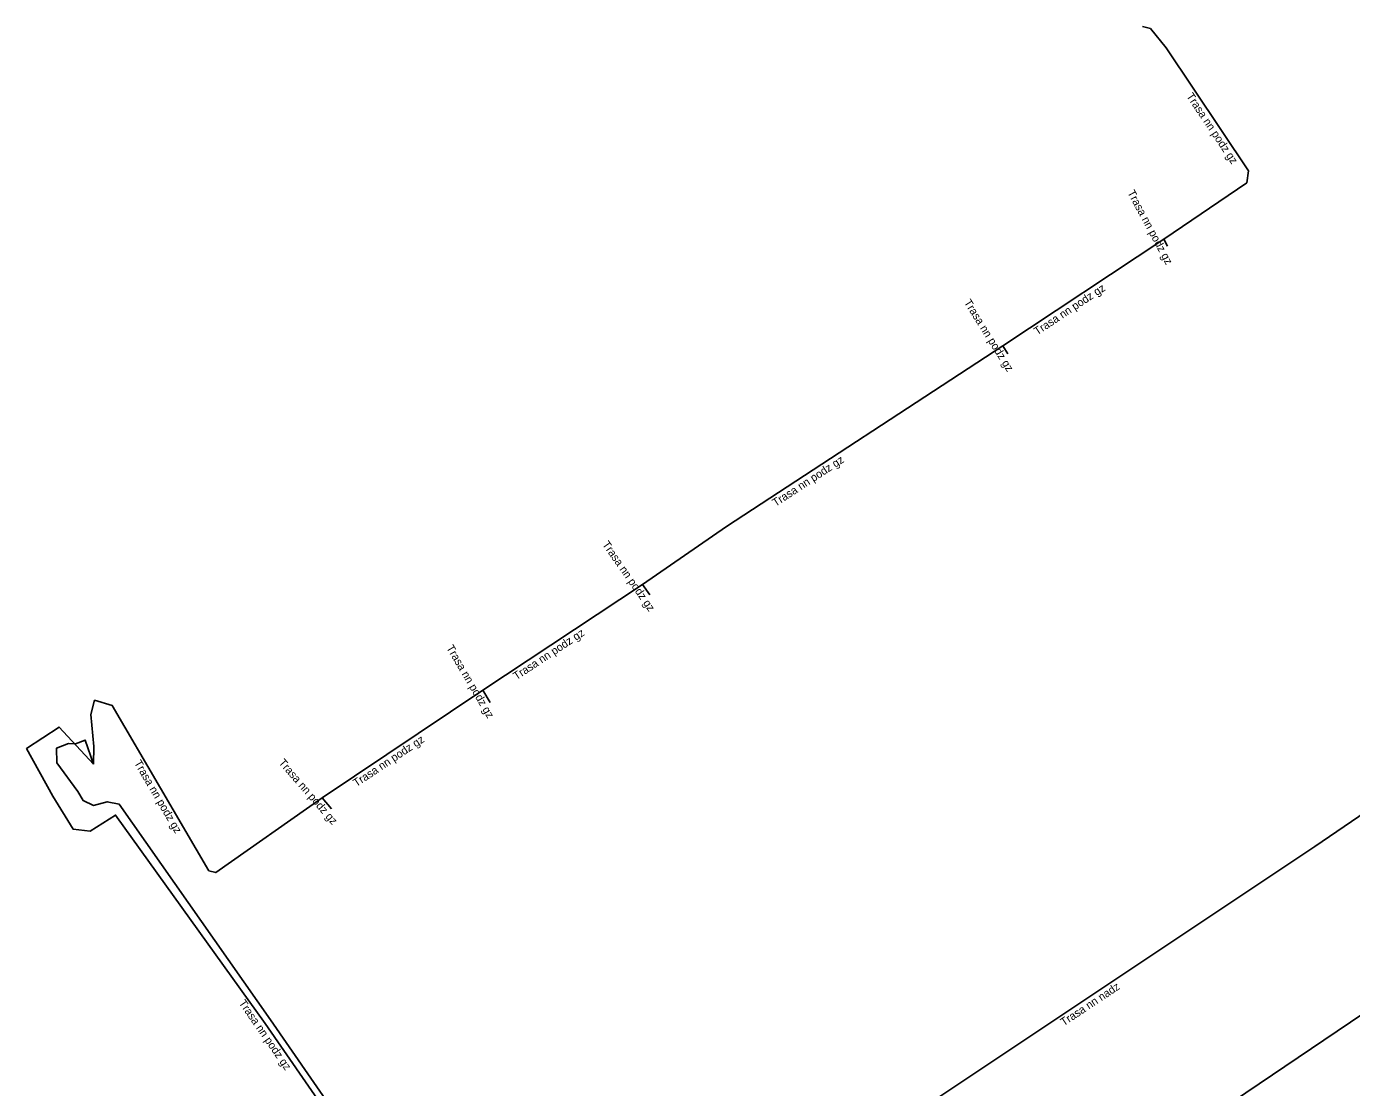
# Model space of a CAD drawing. Extents: x -468149 to -467677, y -1100197 to -1099840.
# Drawn here: x -468013.8 to -467931, y -1100006.5 to -1099940.2 of the extents above; entities that cross this region are included whole.
import ezdxf

# ---------------------------------------------------------------- set-up
doc = ezdxf.new("R2010")
doc.units = 0
for name, color, linetype in [('Popiskový text - Ostatní atributy Trasy', 7, 'Continuous'), ('Spojnice NN', 7, 'Continuous'), ('Spojnice VN', 7, 'Continuous')]:
    doc.layers.add(name, color=color, linetype=linetype)

msp = doc.modelspace()

# ---------------------------------------------------------------- linework, layer by layer
at = {"layer": 'Spojnice NN'}
for points in [[(-467942.72, -1099953.52), (-467937.54, -1099950), (-467937.44, -1099949.26), (-467942.57, -1099941.57), (-467943.562, -1099940.355), (-467944.06, -1099940.234)], [(-467952.772, -1099960.181), (-467942.72, -1099953.52)], [(-467942.72, -1099953.52), (-467942.49, -1099953.95)], [(-467975.299, -1099975.091), (-467970.04, -1099971.48), (-467952.772, -1099960.181)], [(-467952.772, -1099960.181), (-467952.46, -1099960.68)], [(-467985.26, -1099981.7), (-467975.299, -1099975.091)], [(-467975.299, -1099975.091), (-467974.84, -1099975.75)], [(-467911.814, -1099976.83), (-467933.282, -1099991.465)], [(-467995.31, -1099988.42), (-467985.26, -1099981.7)], [(-467985.26, -1099981.7), (-467984.81, -1099982.47)], [(-468009.576, -1099986.317), (-468009.556, -1099985.225), (-468009.755, -1099983.214), (-468009.519, -1099982.327), (-468008.414, -1099982.653), (-468002.38, -1099992.98), (-468001.95, -1099993.1), (-467995.31, -1099988.42)], [(-467977.61, -1100021.71), (-467978.753, -1100021.987), (-467982.581, -1100025.05), (-467983.538, -1100024.922), (-467988.219, -1100017.91), (-467998.856, -1100002.534), (-468008.207, -1099989.502), (-468009.795, -1099990.508), (-468010.862, -1099990.383), (-468012.131, -1099988.334), (-468013.77, -1099985.352), (-468011.734, -1099984.01), (-468009.576, -1099986.317)], [(-467995.31, -1099988.42), (-467994.71, -1099989.11)], [(-467933.282, -1099991.465), (-467960.151, -1100009.378)]]:
    msp.add_lwpolyline(points, dxfattribs=at)
at = {"layer": 'Spojnice VN'}
msp.add_lwpolyline([(-467929.47, -1100001.36), (-467948.11, -1100013.96), (-467968.93, -1100028.2), (-467970.46, -1100028.85), (-467974.27, -1100022.77), (-467975.59, -1100020.87), (-467976.39, -1100020.1), (-467977.04, -1100020.26), (-467979, -1100021.66), (-467982.7, -1100024.62), (-467983.3, -1100024.54), (-467987.88, -1100017.68), (-467998.52, -1100002.3), (-468007.98, -1099988.83), (-468008.73, -1099988.67), (-468009.58, -1099988.9), (-468010.24, -1099988.6), (-468010.56, -1099988.04), (-468011.88, -1099986.25), (-468011.89, -1099985.32), (-468011.14, -1099985.04), (-468010.7, -1099985.06), (-468010.11, -1099984.82), (-468009.576, -1099986.317)], dxfattribs=at)

# ---------------------------------------------------------------- texts
at = {"layer": 'Popiskový text - Ostatní atributy Trasy'}
for s, rotation, p in [('Trasa nn podz gz', 303.70726, (-467941.339, -1099944.587)), ('Trasa nn podz gz', 298.1416, (-467945.015, -1099950.609)), ('Trasa nn podz gz', 33.53061, (-467950.633, -1099959.543)), ('Trasa nn podz gz', 302.0157, (-467955.231, -1099957.474)), ('Trasa nn podz gz', 33.198, (-467966.977, -1099970.253)), ('Trasa nn podz gz', 304.85759, (-467977.829, -1099972.597)), ('Trasa nn podz gz', 33.56378, (-467983.164, -1099981.09)), ('Trasa nn podz gz', 300.30268, (-467987.56, -1099979.051)), ('Trasa nn podz gz', 33.76893, (-467993.161, -1099987.765)), ('Trasa nn podz gz', 311.00909, (-467998.056, -1099986.253)), ('Trasa nn podz gz', 300.2985, (-468007.068, -1099986.245)), ('Trasa nn nadz', 33.69056, (-467948.975, -1100002.708)), ('Trasa nn podz gz', 304.67519, (-468000.534, -1100001.251))]:
    msp.add_text(s, height=0.5, rotation=rotation, dxfattribs=at).set_placement(p)

doc.saveas('drawing.dxf')
